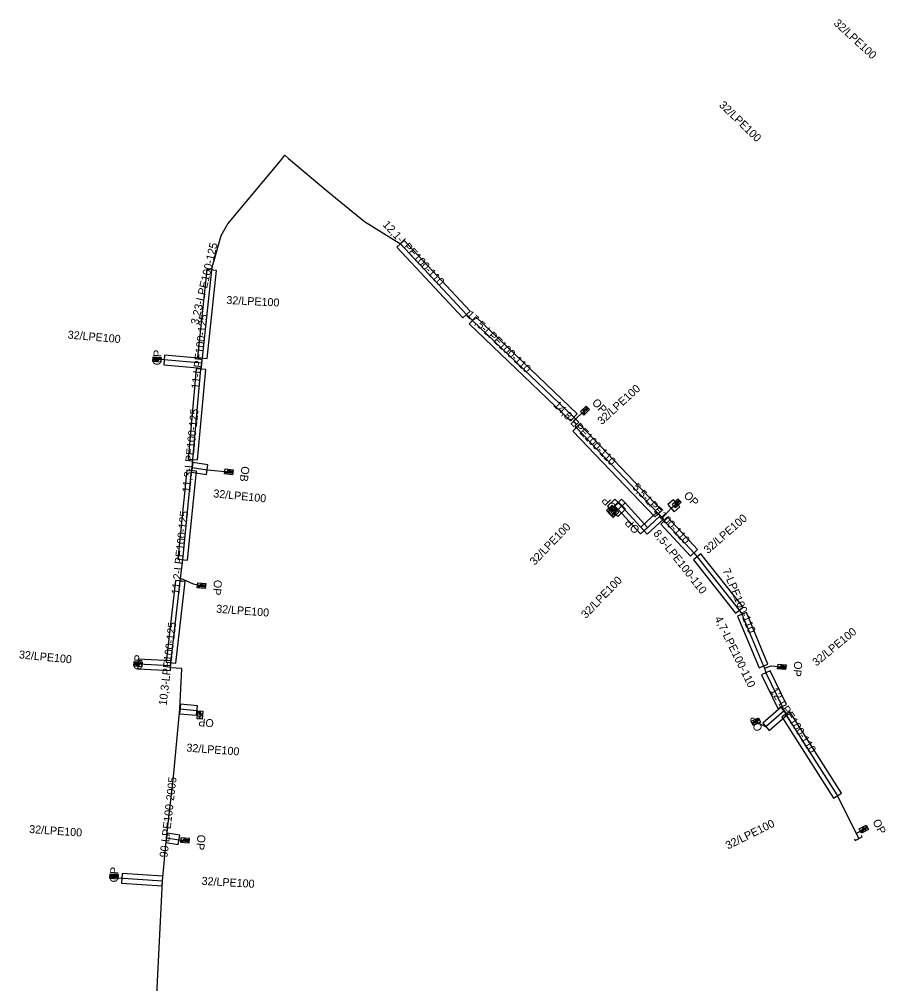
# Model space of a CAD drawing. Extents: x -762921 to -762499, y -1152946 to -1152170.
# Drawn here: x -762775.5 to -762667.3, y -1152366.3 to -1152245.8 of the extents above; entities that cross this region are included whole.
import ezdxf

# ---------------------------------------------------------------- set-up
doc = ezdxf.new("R2010")
doc.units = 0
for name, color, linetype in [('Vrstva 21', 7, 'Continuous'), ('Vrstva 23', 7, 'Continuous'), ('Vrstva 29', 7, 'Continuous'), ('Vrstva 31', 7, 'Continuous'), ('Vrstva 32', 7, 'Continuous')]:
    doc.layers.add(name, color=color, linetype=linetype)

msp = doc.modelspace()

# ---------------------------------------------------------------- linework, layer by layer
at = {"layer": 'Vrstva 21'}
for points in [[(-762758.35, -1152367.62), (-762758.14, -1152363.48), (-762757.65, -1152353.44), (-762757.15, -1152348.04), (-762756.28, -1152340.43), (-762755.48, -1152331.93), (-762755.22, -1152326.89), (-762756.67, -1152326.78), (-762756.64, -1152326.53), (-762756.6, -1152326.16), (-762755.43, -1152315.96), (-762755.39, -1152315.59), (-762755.12, -1152313.29), (-762754.02, -1152302.16), (-762753.95, -1152301.75), (-762753.86, -1152300.78), (-762752.85, -1152289.49), (-762752.74, -1152288.74), (-762752.67, -1152288.08), (-762751.51, -1152277.1), (-762751.35, -1152276.45), (-762751.22, -1152275.89), (-762750.34, -1152272.79), (-762749.48, -1152271.32), (-762742.9, -1152263.45), (-762742.37, -1152262.75)], [(-762742.37, -1152262.75), (-762741.92, -1152263.16), (-762736.98, -1152267.33), (-762732.43, -1152271.04), (-762727.93, -1152273.81), (-762719.69, -1152282.66), (-762718.94, -1152283.39), (-762706.27, -1152295.49), (-762705.64, -1152296.1), (-762705.96, -1152296.38), (-762706.16, -1152296.6), (-762705.97, -1152296.81), (-762695.72, -1152307.54), (-762695.5, -1152307.79), (-762695.25, -1152308.09), (-762694.99, -1152308.42), (-762691.28, -1152312.43), (-762690.88, -1152312.93), (-762685.62, -1152319.59), (-762685.29, -1152320.1), (-762682.6, -1152326.57), (-762682.49, -1152326.82), (-762682.31, -1152327.43), (-762680.25, -1152331.63), (-762680.01, -1152332.16), (-762679.8, -1152332.61), (-762673.36, -1152342.77), (-762671.02, -1152347.49), (-762670.71, -1152348.14)]]:
    msp.add_lwpolyline(points, dxfattribs=at)
at = {"layer": 'Vrstva 23'}
msp.add_lwpolyline([(-762671.247, -1152348.174), (-762671.161, -1152348.355), (-762670.258, -1152347.925), (-762670.344, -1152347.744)], dxfattribs=at)
at = {"layer": 'Vrstva 29'}
for points in [[(-762728.37, -1152274.22), (-762720.13, -1152283.07), (-762719.25, -1152282.25), (-762727.49, -1152273.4)], [(-762752.11, -1152277.04), (-762753.27, -1152288.02), (-762752.07, -1152288.14), (-762750.91, -1152277.16)], [(-762719.35, -1152283.82), (-762706.68, -1152295.92), (-762705.86, -1152295.06), (-762718.53, -1152282.96)], [(-762752.69, -1152288.14), (-762757.4, -1152287.73), (-762757.5, -1152288.93), (-762752.79, -1152289.34)], [(-762753.45, -1152289.44), (-762754.46, -1152300.73), (-762753.26, -1152300.83), (-762752.25, -1152289.54)], [(-762695.29, -1152307.13), (-762705.54, -1152296.4), (-762706.4, -1152297.22), (-762696.15, -1152307.95)], [(-762754.04, -1152302.34), (-762752.15, -1152302.63), (-762751.97, -1152301.45), (-762753.86, -1152301.16)], [(-762754.62, -1152302.1), (-762755.72, -1152313.23), (-762754.52, -1152313.35), (-762753.42, -1152302.22)], [(-762701.22, -1152307.45), (-762700.34, -1152306.58), (-762701.18, -1152305.72), (-762702.06, -1152306.59)], [(-762700.81, -1152307.9), (-762699.85, -1152306.99), (-762700.68, -1152306.12), (-762701.63, -1152307.03)], [(-762701.19, -1152306.56), (-762700.75, -1152307.02), (-762699.89, -1152306.2), (-762700.33, -1152305.74)], [(-762697.08, -1152309.25), (-762699.88, -1152306.2), (-762700.76, -1152307.01), (-762697.96, -1152310.07)], [(-762693.75, -1152307.31), (-762693.05, -1152306.7), (-762693.83, -1152305.8), (-762694.53, -1152306.41)], [(-762695.91, -1152307.35), (-762697.93, -1152309.22), (-762697.11, -1152310.1), (-762695.09, -1152308.23)], [(-762695.43, -1152308.83), (-762691.72, -1152312.84), (-762690.84, -1152312.02), (-762694.55, -1152308.01)], [(-762691.35, -1152313.3), (-762686.09, -1152319.96), (-762685.15, -1152319.22), (-762690.41, -1152312.56)], [(-762756.03, -1152315.89), (-762757.2, -1152326.09), (-762756, -1152326.23), (-762754.83, -1152316.03)], [(-762685.84, -1152320.33), (-762683.15, -1152326.8), (-762682.05, -1152326.34), (-762684.74, -1152319.87)], [(-762756.61, -1152325.93), (-762760.67, -1152325.73), (-762760.73, -1152326.93), (-762756.67, -1152327.13)], [(-762682.85, -1152327.69), (-762680.79, -1152331.89), (-762679.71, -1152331.37), (-762681.77, -1152327.17)], [(-762755.54, -1152332.53), (-762753.42, -1152332.73), (-762753.3, -1152331.53), (-762755.42, -1152331.33)], [(-762680.4, -1152331.71), (-762682.69, -1152333.71), (-762681.91, -1152334.61), (-762679.62, -1152332.61)], [(-762680.31, -1152332.93), (-762673.87, -1152343.09), (-762672.85, -1152342.45), (-762679.29, -1152332.29)], [(-762757.25, -1152348.63), (-762755.7, -1152348.88), (-762755.5, -1152347.7), (-762757.05, -1152347.45)], [(-762757.61, -1152352.84), (-762762.7, -1152352.49), (-762762.79, -1152353.69), (-762757.69, -1152354.04)]]:
    msp.add_lwpolyline(points, close=True, dxfattribs=at)
at = {"layer": 'Vrstva 31'}
for points in [[(-762752.74, -1152288.74), (-762757.45, -1152288.33), (-762758.32, -1152288.27)], [(-762705.96, -1152296.38), (-762706.32, -1152295.94), (-762704.9, -1152294.65)], [(-762753.95, -1152301.75), (-762752.06, -1152302.04), (-762749.36, -1152302.31)], [(-762700.32, -1152306.61), (-762700.76, -1152306.15), (-762701.64, -1152307.02)], [(-762695.25, -1152308.09), (-762694.14, -1152306.86), (-762693.44, -1152306.25)], [(-762700.29, -1152306.65), (-762700.32, -1152306.61), (-762701.22, -1152307.47)], [(-762695.5, -1152307.79), (-762697.52, -1152309.66), (-762700.29, -1152306.65)], [(-762755.39, -1152315.59), (-762753.84, -1152316.32), (-762752.78, -1152316.53)], [(-762756.64, -1152326.53), (-762760.7, -1152326.33)], [(-762682.49, -1152326.82), (-762681.66, -1152326.54), (-762680.31, -1152326.68)], [(-762755.48, -1152331.93), (-762753.36, -1152332.13), (-762753.02, -1152332.35), (-762752.97, -1152332.68)], [(-762680.01, -1152332.16), (-762682.3, -1152334.16), (-762683.55, -1152333.53)], [(-762671.02, -1152347.49), (-762670.08, -1152346.96)], [(-762757.15, -1152348.04), (-762755.6, -1152348.29), (-762754.84, -1152348.35)], [(-762757.65, -1152353.44), (-762763.2, -1152353.06), (-762763.71, -1152352.86)]]:
    msp.add_lwpolyline(points, dxfattribs=at)
at = {"layer": 'Vrstva 32'}
for p, q in [((-762758.707, -1152288.068), (-762758.731, -1152288.417)), ((-762758.718, -1152288.232), (-762758.518, -1152288.246)), ((-762758.53, -1152288.431), (-762758.506, -1152288.082)), ((-762758.132, -1152288.458), (-762758.108, -1152288.109)), ((-762704.49, -1152294.5), (-762704.732, -1152294.247)), ((-762705.166, -1152294.662), (-762704.924, -1152294.915)), ((-762704.877, -1152294.386), (-762704.636, -1152294.639)), ((-762704.604, -1152294.381), (-762704.75, -1152294.52)), ((-762749.538, -1152302.113), (-762749.579, -1152302.46)), ((-762749.141, -1152302.16), (-762749.183, -1152302.508)), ((-762748.964, -1152302.368), (-762749.163, -1152302.344)), ((-762748.984, -1152302.531), (-762748.942, -1152302.184)), ((-762693.706, -1152306.264), (-762693.462, -1152306.515)), ((-762693.42, -1152305.986), (-762693.176, -1152306.237)), ((-762693.147, -1152305.978), (-762693.291, -1152306.118)), ((-762693.032, -1152306.097), (-762693.276, -1152305.846)), ((-762702.048, -1152307.177), (-762701.802, -1152307.426)), ((-762701.932, -1152307.294), (-762701.789, -1152307.153)), ((-762701.659, -1152307.284), (-762701.905, -1152307.035)), ((-762701.375, -1152307.004), (-762701.621, -1152306.755)), ((-762701.243, -1152307.734), (-762701.485, -1152307.481)), ((-762700.955, -1152307.458), (-762701.197, -1152307.205)), ((-762701.63, -1152307.62), (-762701.389, -1152307.873)), ((-762701.516, -1152307.739), (-762701.371, -1152307.6)), ((-762752.965, -1152316.339), (-762752.994, -1152316.687)), ((-762752.567, -1152316.372), (-762752.597, -1152316.721)), ((-762752.383, -1152316.573), (-762752.583, -1152316.556)), ((-762752.396, -1152316.737), (-762752.367, -1152316.389)), ((-762761.091, -1152326.135), (-762761.108, -1152326.485)), ((-762761.099, -1152326.3), (-762760.898, -1152326.31)), ((-762760.907, -1152326.495), (-762760.89, -1152326.145)), ((-762760.509, -1152326.515), (-762760.492, -1152326.165)), ((-762680.494, -1152326.488), (-762680.525, -1152326.837)), ((-762680.097, -1152326.523), (-762680.128, -1152326.872)), ((-762679.913, -1152326.725), (-762680.113, -1152326.707)), ((-762679.927, -1152326.889), (-762679.897, -1152326.541)), ((-762752.78, -1152332.495), (-762753.128, -1152332.467)), ((-762753.176, -1152333.065), (-762752.827, -1152333.093)), ((-762752.811, -1152332.893), (-762753.16, -1152332.865)), ((-762753.012, -1152333.078), (-762752.996, -1152332.878)), ((-762683.986, -1152333.532), (-762683.844, -1152333.852)), ((-762683.919, -1152333.683), (-762683.736, -1152333.601)), ((-762683.661, -1152333.771), (-762683.803, -1152333.451)), ((-762683.296, -1152333.609), (-762683.438, -1152333.289)), ((-762670.339, -1152346.901), (-762670.174, -1152347.209)), ((-762669.988, -1152346.712), (-762669.822, -1152347.02)), ((-762669.723, -1152346.779), (-762669.9, -1152346.875)), ((-762669.645, -1152346.925), (-762669.811, -1152346.616)), ((-762755.023, -1152348.157), (-762755.055, -1152348.506)), ((-762754.626, -1152348.194), (-762754.658, -1152348.542)), ((-762754.442, -1152348.396), (-762754.643, -1152348.378)), ((-762754.457, -1152348.561), (-762754.426, -1152348.212)), ((-762764.101, -1152352.664), (-762764.119, -1152353.014)), ((-762764.109, -1152352.829), (-762763.908, -1152352.839)), ((-762763.918, -1152353.024), (-762763.9, -1152352.675)), ((-762763.519, -1152353.045), (-762763.501, -1152352.695))]:
    msp.add_line(p, q, dxfattribs=at)
for points in [[(-762758.798, -1152287.936), (-762757.8, -1152288.005), (-762757.841, -1152288.604), (-762758.839, -1152288.535), (-762758.798, -1152287.936)], [(-762758.407, -1152288.088), (-762758.425, -1152288.339), (-762758.414, -1152288.389), (-762758.385, -1152288.424), (-762758.345, -1152288.444), (-762758.316, -1152288.446), (-762758.273, -1152288.432), (-762758.241, -1152288.401), (-762758.224, -1152288.353), (-762758.207, -1152288.102)], [(-762758.108, -1152288.109), (-762757.978, -1152288.118), (-762757.938, -1152288.138), (-762757.924, -1152288.155), (-762757.912, -1152288.189), (-762757.916, -1152288.239), (-762757.932, -1152288.271), (-762757.948, -1152288.286), (-762757.991, -1152288.3), (-762758.121, -1152288.291)], [(-762704.332, -1152294.521), (-762705.054, -1152295.212), (-762705.469, -1152294.779), (-762704.746, -1152294.087), (-762704.332, -1152294.521)], [(-762704.924, -1152294.915), (-762705.018, -1152295.004), (-762705.06, -1152295.021), (-762705.082, -1152295.02), (-762705.115, -1152295.006), (-762705.149, -1152294.97), (-762705.162, -1152294.936), (-762705.162, -1152294.914), (-762705.144, -1152294.873), (-762705.05, -1152294.783)], [(-762704.707, -1152294.707), (-762704.881, -1152294.526), (-762704.925, -1152294.5), (-762704.97, -1152294.498), (-762705.012, -1152294.514), (-762705.033, -1152294.535), (-762705.051, -1152294.576), (-762705.05, -1152294.62), (-762705.026, -1152294.665), (-762704.852, -1152294.846)], [(-762748.899, -1152302.667), (-762749.892, -1152302.548), (-762749.821, -1152301.953), (-762748.828, -1152302.072), (-762748.899, -1152302.667)], [(-762749.579, -1152302.46), (-762749.708, -1152302.445), (-762749.748, -1152302.423), (-762749.761, -1152302.405), (-762749.771, -1152302.371), (-762749.765, -1152302.321), (-762749.747, -1152302.29), (-762749.73, -1152302.276), (-762749.687, -1152302.264), (-762749.558, -1152302.279)], [(-762749.281, -1152302.496), (-762749.252, -1152302.247), (-762749.26, -1152302.196), (-762749.286, -1152302.16), (-762749.326, -1152302.138), (-762749.355, -1152302.134), (-762749.399, -1152302.146), (-762749.431, -1152302.176), (-762749.451, -1152302.223), (-762749.481, -1152302.472)], [(-762692.873, -1152306.116), (-762693.59, -1152306.814), (-762694.008, -1152306.384), (-762693.291, -1152305.686), (-762692.873, -1152306.116)], [(-762693.247, -1152306.306), (-762693.422, -1152306.126), (-762693.466, -1152306.1), (-762693.511, -1152306.098), (-762693.553, -1152306.115), (-762693.574, -1152306.136), (-762693.592, -1152306.177), (-762693.59, -1152306.221), (-762693.566, -1152306.266), (-762693.391, -1152306.446)], [(-762702.207, -1152307.158), (-762701.496, -1152306.455), (-762701.074, -1152306.882), (-762701.785, -1152307.585), (-762702.207, -1152307.158)], [(-762701.834, -1152306.966), (-762701.658, -1152307.144), (-762701.614, -1152307.169), (-762701.568, -1152307.171), (-762701.527, -1152307.154), (-762701.506, -1152307.133), (-762701.488, -1152307.092), (-762701.491, -1152307.048), (-762701.515, -1152307.003), (-762701.692, -1152306.824)], [(-762701.789, -1152307.599), (-762701.066, -1152306.908), (-762700.652, -1152307.341), (-762701.375, -1152308.032), (-762701.789, -1152307.599)], [(-762701.621, -1152306.755), (-762701.529, -1152306.663), (-762701.487, -1152306.646), (-762701.465, -1152306.647), (-762701.432, -1152306.66), (-762701.397, -1152306.696), (-762701.383, -1152306.729), (-762701.383, -1152306.751), (-762701.401, -1152306.793), (-762701.493, -1152306.884)], [(-762701.414, -1152307.413), (-762701.24, -1152307.594), (-762701.196, -1152307.62), (-762701.151, -1152307.622), (-762701.109, -1152307.606), (-762701.088, -1152307.586), (-762701.069, -1152307.544), (-762701.071, -1152307.5), (-762701.095, -1152307.455), (-762701.268, -1152307.274)], [(-762701.197, -1152307.205), (-762701.103, -1152307.116), (-762701.061, -1152307.099), (-762701.039, -1152307.1), (-762701.006, -1152307.114), (-762700.971, -1152307.15), (-762700.958, -1152307.184), (-762700.958, -1152307.206), (-762700.977, -1152307.247), (-762701.071, -1152307.337)], [(-762693.462, -1152306.515), (-762693.555, -1152306.606), (-762693.597, -1152306.623), (-762693.619, -1152306.622), (-762693.652, -1152306.608), (-762693.687, -1152306.572), (-762693.7, -1152306.538), (-762693.7, -1152306.517), (-762693.682, -1152306.475), (-762693.589, -1152306.384)], [(-762752.307, -1152316.87), (-762753.304, -1152316.787), (-762753.254, -1152316.189), (-762752.257, -1152316.272), (-762752.307, -1152316.87)], [(-762752.994, -1152316.687), (-762753.124, -1152316.676), (-762753.164, -1152316.656), (-762753.178, -1152316.639), (-762753.189, -1152316.605), (-762753.185, -1152316.555), (-762753.168, -1152316.523), (-762753.152, -1152316.509), (-762753.109, -1152316.495), (-762752.979, -1152316.506)], [(-762752.695, -1152316.712), (-762752.674, -1152316.462), (-762752.684, -1152316.412), (-762752.712, -1152316.377), (-762752.753, -1152316.356), (-762752.782, -1152316.354), (-762752.825, -1152316.367), (-762752.857, -1152316.398), (-762752.875, -1152316.445), (-762752.896, -1152316.696)], [(-762761.185, -1152326.006), (-762760.186, -1152326.055), (-762760.215, -1152326.654), (-762761.214, -1152326.605), (-762761.185, -1152326.006)], [(-762760.791, -1152326.15), (-762760.804, -1152326.401), (-762760.792, -1152326.45), (-762760.763, -1152326.485), (-762760.722, -1152326.504), (-762760.693, -1152326.505), (-762760.65, -1152326.491), (-762760.619, -1152326.459), (-762760.603, -1152326.411), (-762760.591, -1152326.16)], [(-762760.492, -1152326.165), (-762760.362, -1152326.171), (-762760.321, -1152326.19), (-762760.307, -1152326.207), (-762760.294, -1152326.241), (-762760.297, -1152326.291), (-762760.312, -1152326.323), (-762760.328, -1152326.338), (-762760.371, -1152326.353), (-762760.501, -1152326.347)], [(-762679.839, -1152327.023), (-762680.835, -1152326.935), (-762680.782, -1152326.337), (-762679.786, -1152326.425), (-762679.839, -1152327.023)], [(-762680.525, -1152326.837), (-762680.655, -1152326.825), (-762680.695, -1152326.805), (-762680.708, -1152326.787), (-762680.719, -1152326.753), (-762680.715, -1152326.703), (-762680.698, -1152326.672), (-762680.682, -1152326.657), (-762680.639, -1152326.644), (-762680.509, -1152326.655)], [(-762680.226, -1152326.863), (-762680.204, -1152326.613), (-762680.214, -1152326.563), (-762680.242, -1152326.527), (-762680.282, -1152326.507), (-762680.311, -1152326.504), (-762680.354, -1152326.517), (-762680.386, -1152326.548), (-762680.404, -1152326.595), (-762680.426, -1152326.845)], [(-762753.309, -1152333.155), (-762753.229, -1152332.158), (-762752.631, -1152332.206), (-762752.711, -1152333.203), (-762753.309, -1152333.155)], [(-762753.152, -1152332.766), (-762752.902, -1152332.786), (-762752.852, -1152332.776), (-762752.817, -1152332.748), (-762752.797, -1152332.707), (-762752.794, -1152332.678), (-762752.808, -1152332.635), (-762752.838, -1152332.604), (-762752.886, -1152332.586), (-762753.136, -1152332.566)], [(-762753.128, -1152332.467), (-762753.118, -1152332.338), (-762753.098, -1152332.297), (-762753.081, -1152332.283), (-762753.047, -1152332.272), (-762752.997, -1152332.276), (-762752.965, -1152332.293), (-762752.95, -1152332.309), (-762752.937, -1152332.352), (-762752.947, -1152332.482)], [(-762684.128, -1152333.459), (-762683.214, -1152333.053), (-762682.971, -1152333.601), (-762683.885, -1152334.007), (-762684.128, -1152333.459)], [(-762683.712, -1152333.41), (-762683.61, -1152333.64), (-762683.578, -1152333.679), (-762683.536, -1152333.697), (-762683.491, -1152333.695), (-762683.464, -1152333.683), (-762683.433, -1152333.651), (-762683.419, -1152333.609), (-762683.427, -1152333.558), (-762683.528, -1152333.329)], [(-762683.438, -1152333.289), (-762683.319, -1152333.236), (-762683.274, -1152333.234), (-762683.254, -1152333.243), (-762683.227, -1152333.267), (-762683.207, -1152333.313), (-762683.207, -1152333.349), (-762683.214, -1152333.37), (-762683.245, -1152333.402), (-762683.364, -1152333.455)], [(-762669.498, -1152346.987), (-762670.379, -1152347.461), (-762670.663, -1152346.933), (-762669.782, -1152346.459), (-762669.498, -1152346.987)], [(-762670.174, -1152347.209), (-762670.288, -1152347.27), (-762670.333, -1152347.275), (-762670.354, -1152347.268), (-762670.382, -1152347.246), (-762670.406, -1152347.202), (-762670.409, -1152347.166), (-762670.403, -1152347.145), (-762670.374, -1152347.11), (-762670.26, -1152347.049)], [(-762669.909, -1152347.067), (-762670.028, -1152346.846), (-762670.064, -1152346.809), (-762670.107, -1152346.795), (-762670.152, -1152346.8), (-762670.177, -1152346.813), (-762670.206, -1152346.848), (-762670.216, -1152346.891), (-762670.205, -1152346.941), (-762670.086, -1152347.162)], [(-762754.369, -1152348.694), (-762755.365, -1152348.603), (-762755.31, -1152348.005), (-762754.315, -1152348.097), (-762754.369, -1152348.694)], [(-762755.055, -1152348.506), (-762755.184, -1152348.494), (-762755.225, -1152348.473), (-762755.238, -1152348.456), (-762755.249, -1152348.422), (-762755.245, -1152348.372), (-762755.228, -1152348.34), (-762755.211, -1152348.326), (-762755.168, -1152348.313), (-762755.038, -1152348.325)], [(-762754.756, -1152348.533), (-762754.733, -1152348.283), (-762754.743, -1152348.233), (-762754.771, -1152348.197), (-762754.811, -1152348.177), (-762754.84, -1152348.174), (-762754.883, -1152348.187), (-762754.915, -1152348.217), (-762754.934, -1152348.265), (-762754.956, -1152348.515)], [(-762764.194, -1152352.534), (-762763.195, -1152352.586), (-762763.226, -1152353.185), (-762764.225, -1152353.134), (-762764.194, -1152352.534)], [(-762763.801, -1152352.68), (-762763.814, -1152352.93), (-762763.802, -1152352.98), (-762763.773, -1152353.015), (-762763.732, -1152353.034), (-762763.703, -1152353.035), (-762763.66, -1152353.02), (-762763.63, -1152352.989), (-762763.613, -1152352.941), (-762763.6, -1152352.69)], [(-762763.501, -1152352.695), (-762763.372, -1152352.702), (-762763.331, -1152352.721), (-762763.316, -1152352.738), (-762763.304, -1152352.771), (-762763.307, -1152352.821), (-762763.322, -1152352.853), (-762763.338, -1152352.869), (-762763.381, -1152352.883), (-762763.511, -1152352.877)]]:
    msp.add_lwpolyline(points, dxfattribs=at)

# ---------------------------------------------------------------- texts
at = {"layer": 'Vrstva 21'}
msp.add_text('90-LPE100-2005', height=1, rotation=83.47808, dxfattribs=at).set_placement((-762757.04, -1152350.53))
at = {"layer": 'Vrstva 29'}
for s, rotation, p in [('12,1-LPE100-110', 312.95579, (-762730.22, -1152271.48)), ('3,23-LPE100-125', 76.56101, (-762753.19, -1152284)), ('11-LPE100-125', 83.43071, (-762753.08, -1152292)), ('17,5-LPE100-110', 316.31824, (-762719.8, -1152282.78)), ('14,8-LPE100-110', 313.85434, (-762708.9, -1152294.03)), ('11,3-LPE100-125', 84.21276, (-762754.2, -1152304.92)), ('5,5-LPE100-110', 312.7746, (-762699.04, -1152304.29)), ('11,2-LPE100-125', 83.9366, (-762755.55, -1152317.67)), ('8,5-LPE100-110', 308.30132, (-762696.41, -1152310.03)), ('7-LPE100-110', 292.57584, (-762687.75, -1152314.61)), ('4,7-LPE100-110', 296.12685, (-762688.73, -1152320.63)), ('10,3-LPE100-125', 83.37111, (-762757.14, -1152331.55)), ('12-LPE100-110', 302.36891, (-762681.81, -1152329.66))]:
    msp.add_text(s, height=1, rotation=rotation, dxfattribs=at).set_placement(p)
at = {"layer": 'Vrstva 31'}
for rotation, p in [(317.52327, (-762673.92, -1152246.36)), (317.52327, (-762673.92, -1152246.36)), (316.00509, (-762688.22, -1152256.58)), (316.00509, (-762688.22, -1152256.58)), (357.11284, (-762749.69, -1152281.33)), (357.11284, (-762749.69, -1152281.33)), (355.02501, (-762769.52, -1152285.65)), (355.02501, (-762769.52, -1152285.65)), (42.2536, (-762702.79, -1152296.49)), (42.2536, (-762702.79, -1152296.49)), (354.28941, (-762751.34, -1152305.48)), (354.28941, (-762751.34, -1152305.48)), (46.24197, (-762711.18, -1152314.05)), (46.24197, (-762711.18, -1152314.05)), (41.06983, (-762689.54, -1152312.6)), (41.06983, (-762689.54, -1152312.6)), (45.90326, (-762704.78, -1152320.7)), (45.90326, (-762704.78, -1152320.7)), (355.52154, (-762750.98, -1152319.89)), (355.52154, (-762750.98, -1152319.89)), (39.42175, (-762676, -1152326.65)), (39.42175, (-762676, -1152326.65)), (354.49021, (-762775.61, -1152325.61)), (354.49021, (-762775.61, -1152325.61)), (355.66813, (-762754.69, -1152337.25)), (355.66813, (-762754.69, -1152337.25)), (26.4124, (-762687.03, -1152349.51)), (26.4124, (-762687.03, -1152349.51)), (356.08316, (-762774.33, -1152347.43)), (356.08316, (-762774.33, -1152347.43)), (356.62698, (-762752.79, -1152353.9)), (356.62698, (-762752.79, -1152353.9))]:
    msp.add_text('32/LPE100', height=1, rotation=rotation, dxfattribs=at).set_placement(p)
at = {"layer": 'Vrstva 32'}
for s, rotation, p in [('OP', 86.05481, (-762757.87, -1152289.03)), ('OP', 86.05481, (-762757.87, -1152289.03)), ('OP', 313.73407, (-762704.09, -1152293.73)), ('OP', 313.73407, (-762704.09, -1152293.73)), ('OB', 263.1675, (-762747.77, -1152301.56)), ('OB', 263.1675, (-762747.77, -1152301.56)), ('OP', 314.20364, (-762692.64, -1152305.33)), ('OP', 314.20364, (-762692.64, -1152305.33)), ('OP', 134.6726, (-762700.85, -1152306.67)), ('OP', 134.6726, (-762700.85, -1152306.67)), ('OP', 133.69805, (-762697.97, -1152309.46)), ('OP', 133.69805, (-762697.97, -1152309.46)), ('OP', 265.21145, (-762751.21, -1152315.77)), ('OP', 265.21145, (-762751.21, -1152315.77)), ('OP', 87.17983, (-762760.24, -1152327.1)), ('OP', 87.17983, (-762760.24, -1152327.1)), ('OP', 264.94891, (-762678.74, -1152325.93)), ('OP', 264.94891, (-762678.74, -1152325.93)), ('OP', 175.42301, (-762751.21, -1152333.24)), ('OP', 175.42301, (-762751.21, -1152333.24)), ('OP', 113.94539, (-762682.68, -1152334.46)), ('OP', 113.94539, (-762682.68, -1152334.46)), ('OP', 298.27942, (-762669.02, -1152346.02)), ('OP', 298.27942, (-762669.02, -1152346.02)), ('OP', 264.77352, (-762753.27, -1152347.6)), ('OP', 264.77352, (-762753.27, -1152347.6)), ('OP', 87.06509, (-762763.25, -1152353.63)), ('OP', 87.06509, (-762763.25, -1152353.63))]:
    msp.add_text(s, height=1, rotation=rotation, dxfattribs=at).set_placement(p)

doc.saveas('drawing.dxf')
